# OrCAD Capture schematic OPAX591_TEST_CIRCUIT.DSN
size A; title: OPAx591 85V, Precision (1µV/°C), Low-Power (450µA),; rev: 1.0; note: Datasheet: SBOSA47A - FEB '26 REV. JUN '26   EVM: SBOU192 - JUL '17
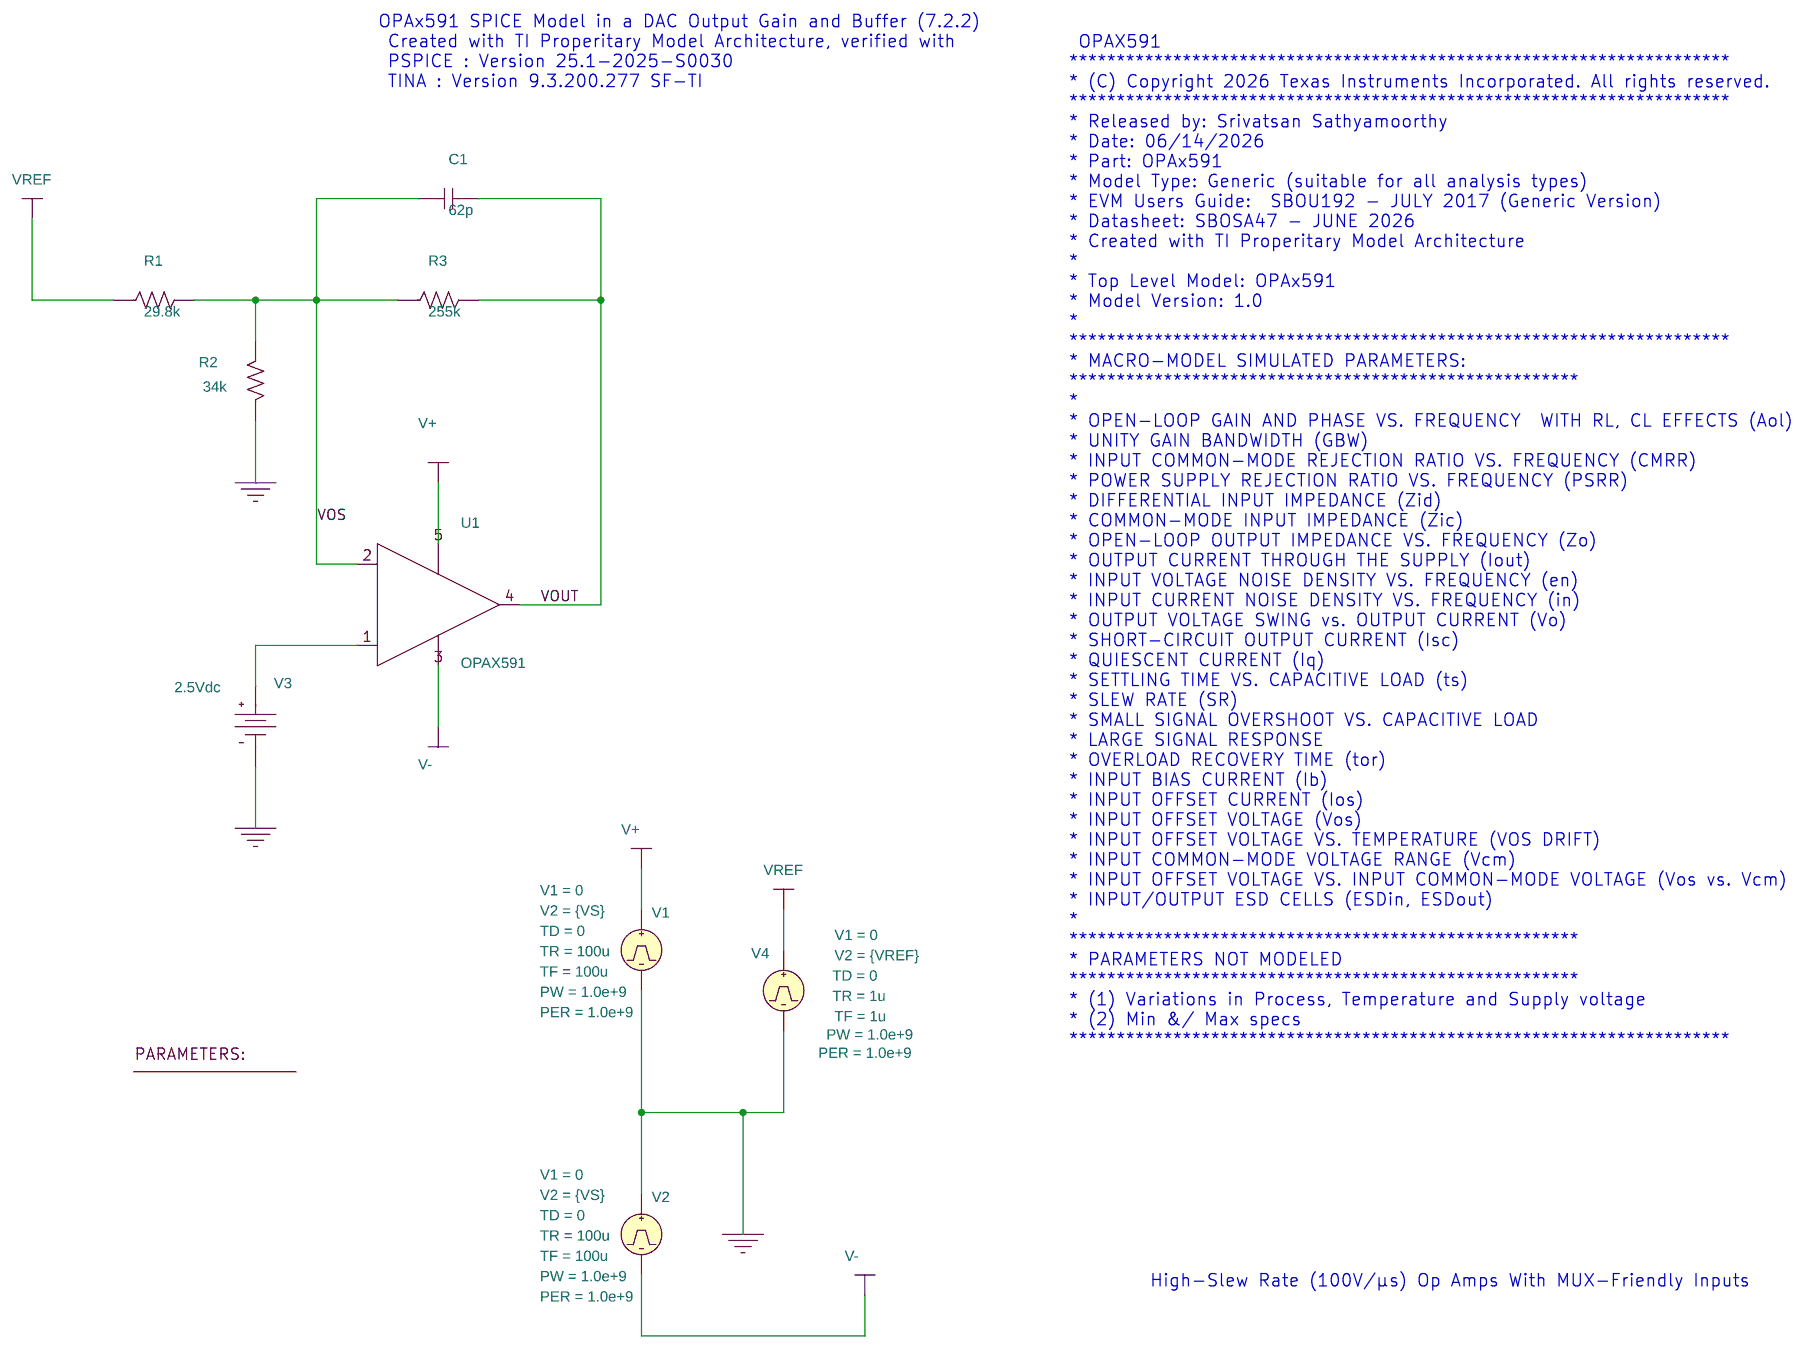
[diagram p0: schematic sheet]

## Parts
1  PARAM
C1  62p  [cap196]
R1  29.8k  [AXRC05]
R2  34k  [AXRC05]
R3  255k  [AXRC05]
U1  OPAX591
V1  VPULSE
V2  VPULSE
V3  VDC
V4  VPULSE

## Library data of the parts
1 = PARAM: VREF: 5; VS: 42.5
C1 = C
R1-R3 = R
U1 = OPAX591
V1 V2 = VPULSE: AC: 0; AppProp: Pulse$Voltage$0$-1; DC: {VS}; PER: 1.0e+9; PW: 1.0e+9; TD: 0; TF: 100u; TR: 100u; V1: 0; V2: {VS}
V3 = VDC: DC: 2.5Vdc
V4 = VPULSE: AC: 0; AppProp: Pulse$Voltage$0$-1; DC: {VREF}; PER: 1.0e+9; PW: 1.0e+9; TD: 0; TF: 1u; TR: 1u; V1: 0; V2: {VREF}

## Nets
0: R2.1 V1.2(-) V2.1(+) V3.1(-) V4.2(-)
V+: U1.5(V+) V1.1(+)
V-: U1.3(V-) V2.2(-)
VOS: C1.1 R1.2 R2.2 R3.1 U1.2(-)
VOUT: C1.2 R3.2 U1.4(OUT)
VREF: R1.1 V4.1(+)
N00510: U1.1(+) V3.0(+)

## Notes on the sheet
- OPAx591 SPICE Model in a DAC Output Gain and Buffer (7.2.2)
   Created with TI Properitary Model Architecture, verified with
   PSPICE : Version 25.1-2025-S0030
   TINA : Version 9.3.200.277 SF-TI
- OPAX591
  **********************************************************************
  * (C) Copyright 2026 Texas Instruments Incorporated. All rights reserved.
  **********************************************************************
  * Released by: Srivatsan Sathyamoorthy
  * Date: 06/14/2026
  * Part: OPAx591
  * Model Type: Generic (suitable for all analysis types)
  * EVM Users Guide:  SBOU192 - JULY 2017 (Generic Version)
  * Datasheet: SBOSA47 - JUNE 2026
  * Created with TI Properitary Model Architecture
  *
  * Top Level Model: OPAx591
  * Model Version: 1.0
  *
  **********************************************************************
  * MACRO-MODEL SIMULATED PARAMETERS:
  ******************************************************
  *
  * OPEN-LOOP GAIN AND PHASE VS. FREQUENCY  WITH RL, CL EFFECTS (Aol)
  * UNITY GAIN BANDWIDTH (GBW)
  * INPUT COMMON-MODE REJECTION RATIO VS. FREQUENCY (CMRR)
  * POWER SUPPLY REJECTION RATIO VS. FREQUENCY (PSRR)
  * DIFFERENTIAL INPUT IMPEDANCE (Zid)
  * COMMON-MODE INPUT IMPEDANCE (Zic)
  * OPEN-LOOP OUTPUT IMPEDANCE VS. FREQUENCY (Zo)
  * OUTPUT CURRENT THROUGH THE SUPPLY (Iout)
  * INPUT VOLTAGE NOISE DENSITY VS. FREQUENCY (en)
  * INPUT CURRENT NOISE DENSITY VS. FREQUENCY (in)
  * OUTPUT VOLTAGE SWING vs. OUTPUT CURRENT (Vo)
  * SHORT-CIRCUIT OUTPUT CURRENT (Isc)
  * QUIESCENT CURRENT (Iq)
  * SETTLING TIME VS. CAPACITIVE LOAD (ts)
  * SLEW RATE (SR)
  * SMALL SIGNAL OVERSHOOT VS. CAPACITIVE LOAD
  * LARGE SIGNAL RESPONSE
  * OVERLOAD RECOVERY TIME (tor)
  * INPUT BIAS CURRENT (Ib)
  * INPUT OFFSET CURRENT (Ios)
  * INPUT OFFSET VOLTAGE (Vos)
  * INPUT OFFSET VOLTAGE VS. TEMPERATURE (VOS DRIFT)
  * INPUT COMMON-MODE VOLTAGE RANGE (Vcm)
  * INPUT OFFSET VOLTAGE VS. INPUT COMMON-MODE VOLTAGE (Vos vs. Vcm)
  * INPUT/OUTPUT ESD CELLS (ESDin, ESDout)
  *
  ******************************************************
  * PARAMETERS NOT MODELED
  ******************************************************
  * (1) Variations in Process, Temperature and Supply voltage
  * (2) Min &/ Max specs
  **********************************************************************
- High-Slew Rate (100V/µs) Op Amps With MUX-Friendly Inputs
